(* Logix 5000 project; controller Test vendor 1 type 14 code 92 rev 33.11; software revision 33.03; part 2 of 2 *)
(* tags used below, declared in another part *)
   S15STH : Banner_S15S_TH_v4;
   Port_Data : Banner_IOL_Port_v4;
   Port : DINT;
   Local_Control : DINT;
   Command_Being_Processed : BOOL;
   Index_Write_Inprocess : INT;
   Inprocess_Index : DINT;
   AOI_Out_Status : Banner_S15S_TH_Float_Out_v4[12];
(* Banner_S15S_TH_Param_v4, continued *)

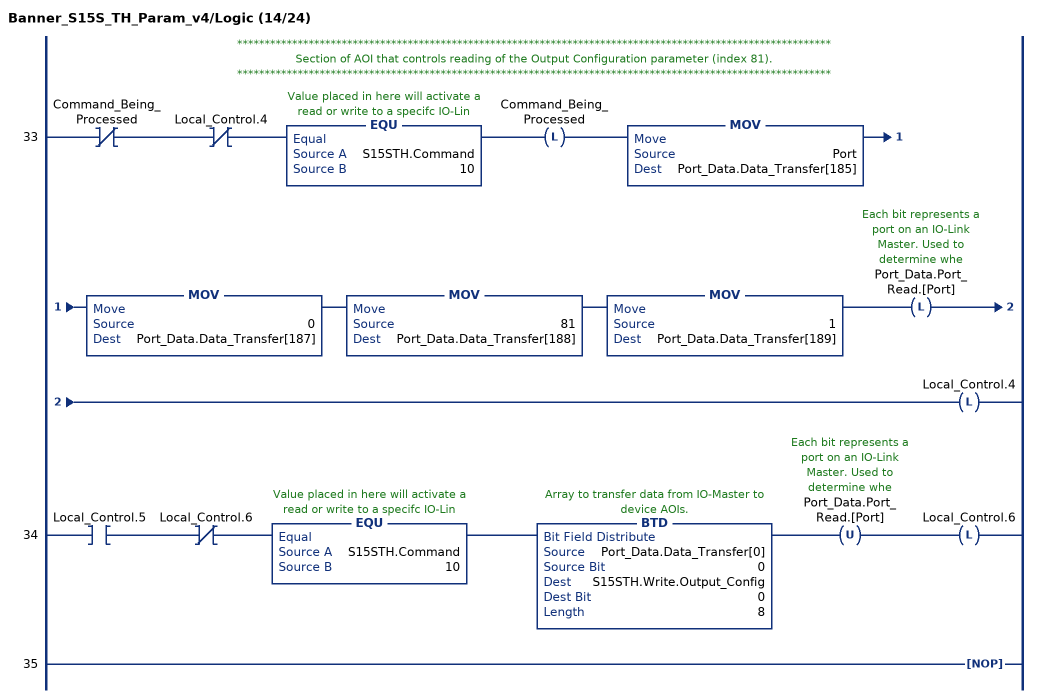
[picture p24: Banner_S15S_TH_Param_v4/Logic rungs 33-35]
   // ************************************************************************************************************
   // Section of AOI that controls reading of the Output Configuration parameter (index 81).
   // ************************************************************************************************************
   33: XIO(Command_Being_Processed)XIO(Local_Control.4)EQU(S15STH.Command,10)OTL(Command_Being_Processed)MOV(Port,Port_Data.Data_Transfer[185])MOV(0,Port_Data.Data_Transfer[187])MOV(81,Port_Data.Data_Transfer[188])MOV(1,Port_Data.Data_Transfer[189])OTL(Port_Data.Port_Read.[Port])OTL(Local_Control.4);
   34: XIC(Local_Control.5)XIO(Local_Control.6)EQU(S15STH.Command,10)BTD(Port_Data.Data_Transfer[0],0,S15STH.Write.Output_Config,0,8)OTU(Port_Data.Port_Read.[Port])OTL(Local_Control.6);
   35: NOP();
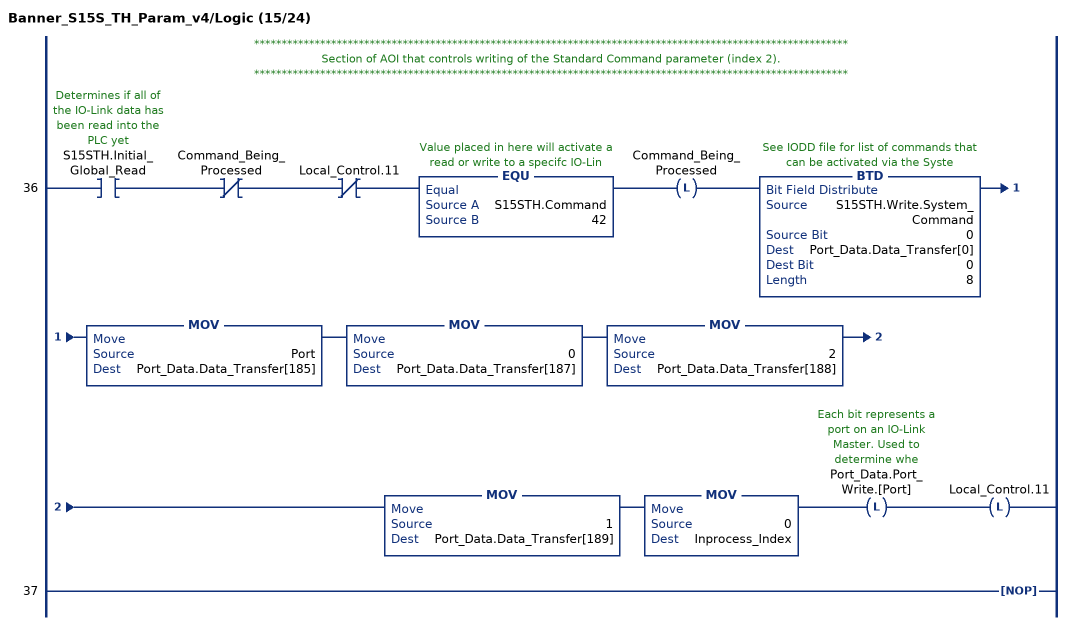
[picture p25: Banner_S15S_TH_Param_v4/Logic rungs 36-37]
   // ************************************************************************************************************
   // Section of AOI that controls writing of the Standard Command parameter (index 2).
   // ************************************************************************************************************
   36: XIC(S15STH.Initial_Global_Read)XIO(Command_Being_Processed)XIO(Local_Control.11)EQU(S15STH.Command,42)OTL(Command_Being_Processed)BTD(S15STH.Write.System_Command,0,Port_Data.Data_Transfer[0],0,8)MOV(Port,Port_Data.Data_Transfer[185])MOV(0,Port_Data.Data_Transfer[187])MOV(2,Port_Data.Data_Transfer[188])MOV(1,Port_Data.Data_Transfer[189])MOV(0,Inprocess_Index)OTL(Port_Data.Port_Write.[Port])OTL(Local_Control.11);
   37: NOP();
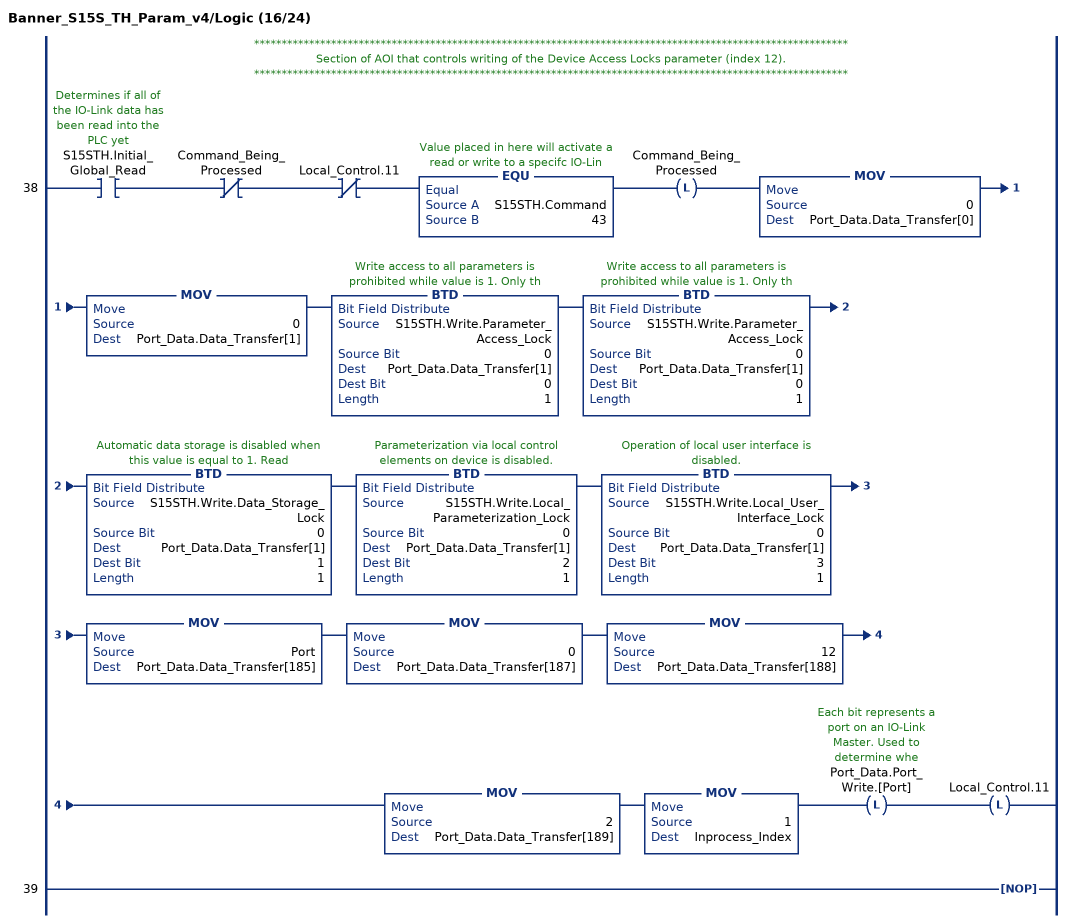
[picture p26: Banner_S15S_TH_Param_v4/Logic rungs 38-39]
   // ************************************************************************************************************
   // Section of AOI that controls writing of the Device Access Locks parameter (index 12).
   // ************************************************************************************************************
   38: XIC(S15STH.Initial_Global_Read)XIO(Command_Being_Processed)XIO(Local_Control.11)EQU(S15STH.Command,43)OTL(Command_Being_Processed)MOV(0,Port_Data.Data_Transfer[0])MOV(0,Port_Data.Data_Transfer[1])BTD(S15STH.Write.Parameter_Access_Lock,0,Port_Data.Data_Transfer[1],0,1)BTD(S15STH.Write.Parameter_Access_Lock,0,Port_Data.Data_Transfer[1],0,1)BTD(S15STH.Write.Data_Storage_Lock,0,Port_Data.Data_Transfer[1],1,1)BTD(S15STH.Write.Local_Parameterization_Lock,0,Port_Data.Data_Transfer[1],2,1)BTD(S15STH.Write.Local_User_Interface_Lock,0,Port_Data.Data_Transfer[1],3,1)MOV(Port,Port_Data.Data_Transfer[185])MOV(0,Port_Data.Data_Transfer[187])MOV(12,Port_Data.Data_Transfer[188])MOV(2,Port_Data.Data_Transfer[189])MOV(1,Inprocess_Index)OTL(Port_Data.Port_Write.[Port])OTL(Local_Control.11);
   39: NOP();
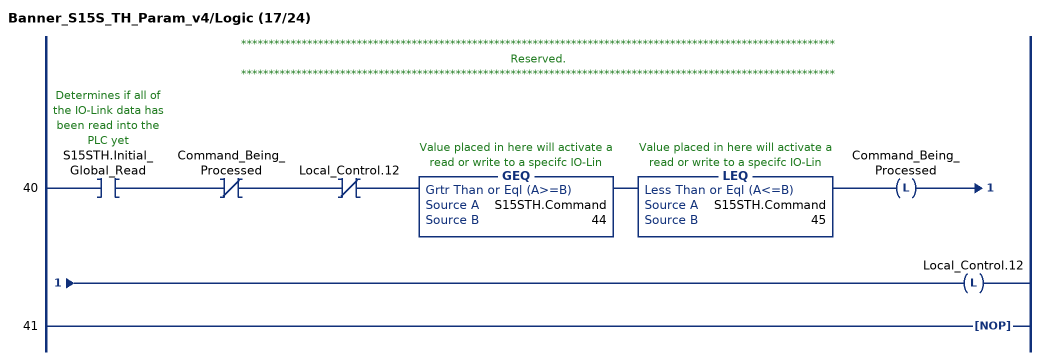
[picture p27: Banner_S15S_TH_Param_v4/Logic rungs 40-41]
   // ************************************************************************************************************
   // Reserved.
   // ************************************************************************************************************
   40: XIC(S15STH.Initial_Global_Read)XIO(Command_Being_Processed)XIO(Local_Control.12)GEQ(S15STH.Command,44)LEQ(S15STH.Command,45)OTL(Command_Being_Processed)OTL(Local_Control.12);
   41: NOP();
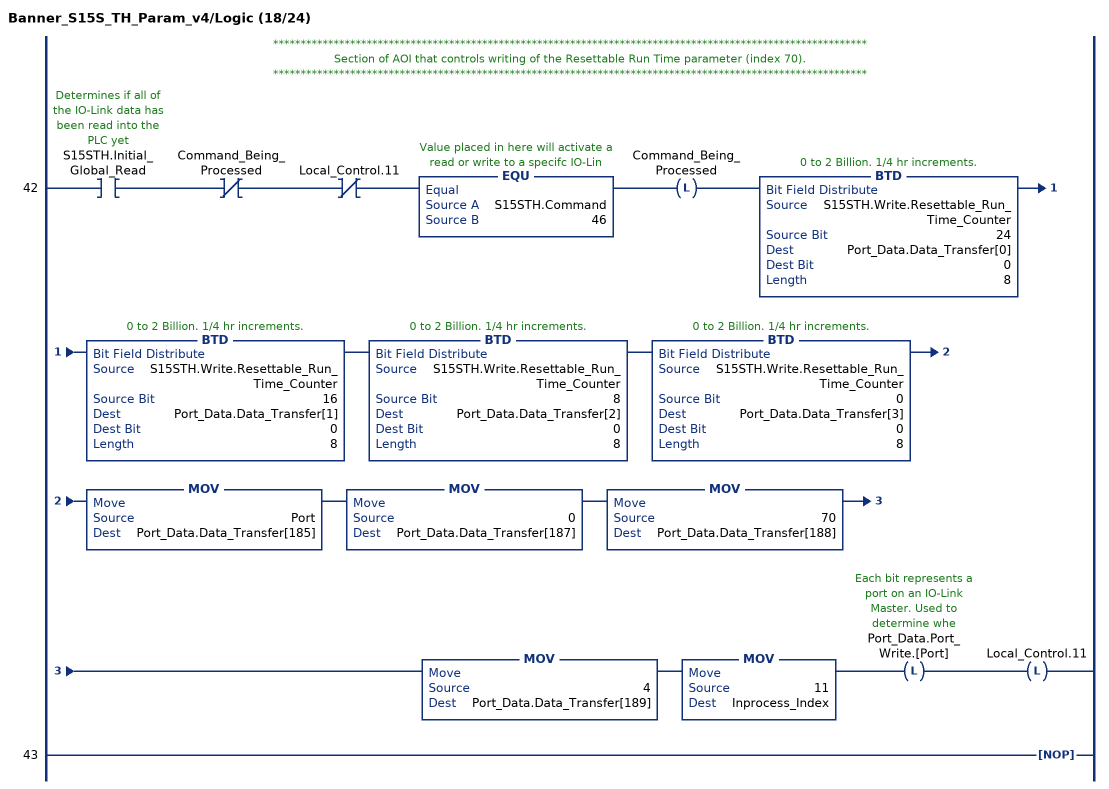
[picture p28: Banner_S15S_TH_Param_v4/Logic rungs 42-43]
   // ************************************************************************************************************
   // Section of AOI that controls writing of the Resettable Run Time parameter (index 70).
   // ************************************************************************************************************
   42: XIC(S15STH.Initial_Global_Read)XIO(Command_Being_Processed)XIO(Local_Control.11)EQU(S15STH.Command,46)OTL(Command_Being_Processed)BTD(S15STH.Write.Resettable_Run_Time_Counter,24,Port_Data.Data_Transfer[0],0,8)BTD(S15STH.Write.Resettable_Run_Time_Counter,16,Port_Data.Data_Transfer[1],0,8)BTD(S15STH.Write.Resettable_Run_Time_Counter,8,Port_Data.Data_Transfer[2],0,8)BTD(S15STH.Write.Resettable_Run_Time_Counter,0,Port_Data.Data_Transfer[3],0,8)MOV(Port,Port_Data.Data_Transfer[185])MOV(0,Port_Data.Data_Transfer[187])MOV(70,Port_Data.Data_Transfer[188])MOV(4,Port_Data.Data_Transfer[189])MOV(11,Inprocess_Index)OTL(Port_Data.Port_Write.[Port])OTL(Local_Control.11);
   43: NOP();
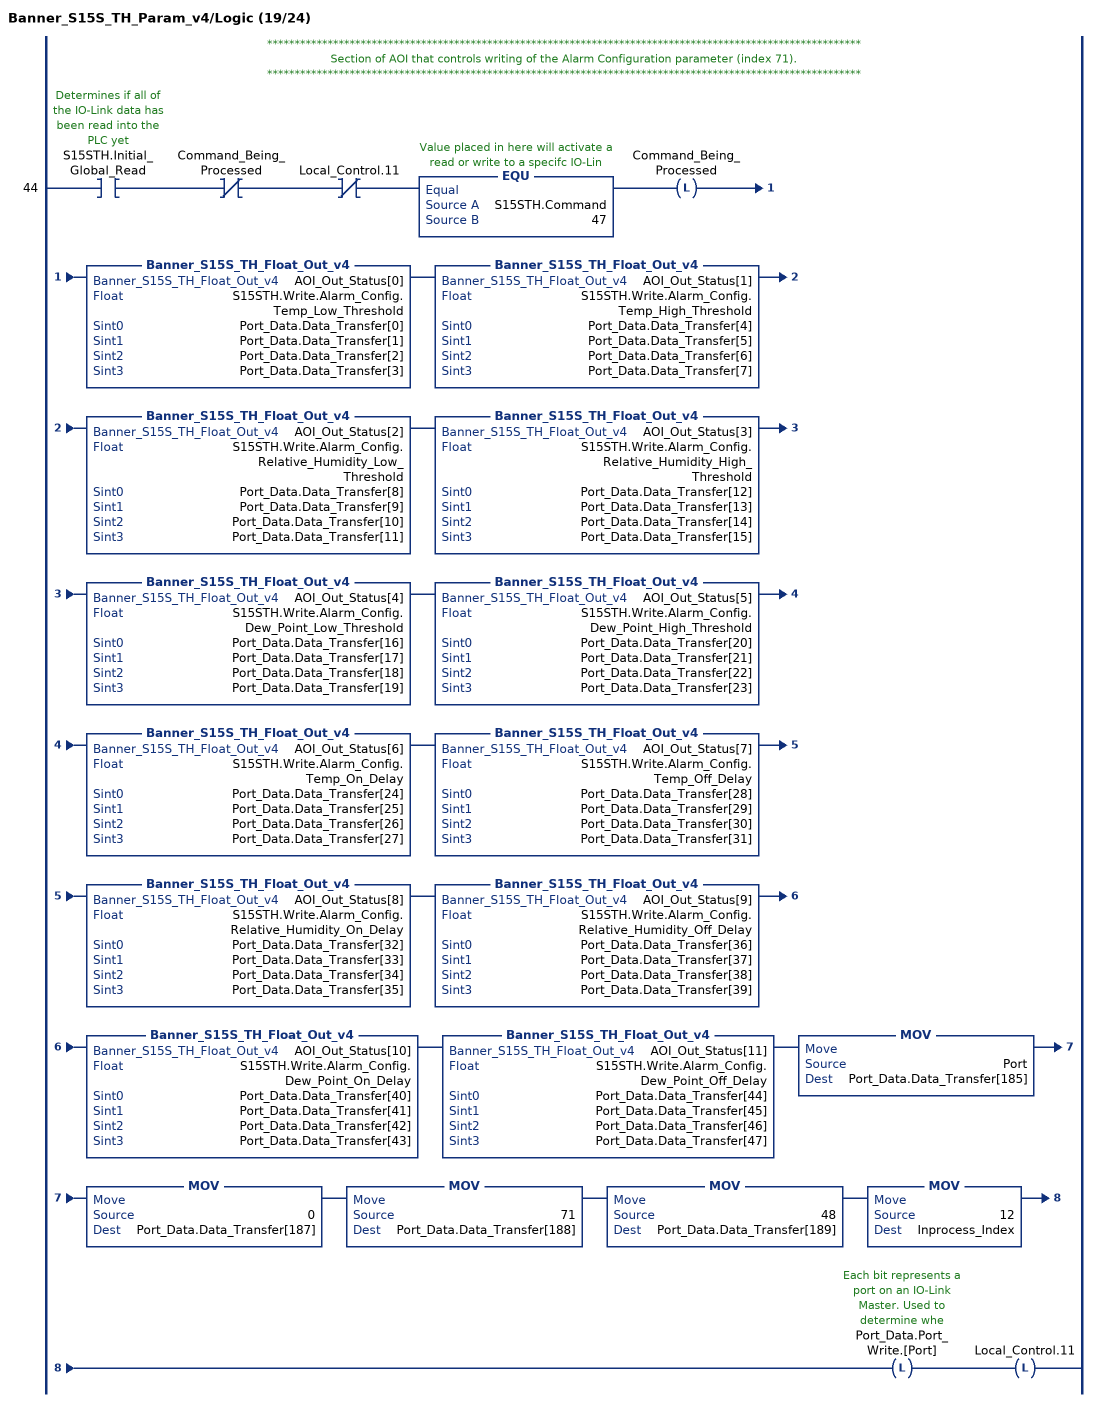
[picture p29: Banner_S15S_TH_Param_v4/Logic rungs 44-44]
   // ************************************************************************************************************
   // Section of AOI that controls writing of the Alarm Configuration parameter (index 71).
   // ************************************************************************************************************
   44: XIC(S15STH.Initial_Global_Read)XIO(Command_Being_Processed)XIO(Local_Control.11)EQU(S15STH.Command,47)OTL(Command_Being_Processed)Banner_S15S_TH_Float_Out_v4(AOI_Out_Status[0],S15STH.Write.Alarm_Config.Temp_Low_Threshold,Port_Data.Data_Transfer[0],Port_Data.Data_Transfer[1],Port_Data.Data_Transfer[2],Port_Data.Data_Transfer[3])Banner_S15S_TH_Float_Out_v4(AOI_Out_Status[1],S15STH.Write.Alarm_Config.Temp_High_Threshold,Port_Data.Data_Transfer[4],Port_Data.Data_Transfer[5],Port_Data.Data_Transfer[6],Port_Data.Data_Transfer[7])Banner_S15S_TH_Float_Out_v4(AOI_Out_Status[2],S15STH.Write.Alarm_Config.Relative_Humidity_Low_Threshold,Port_Data.Data_Transfer[8],Port_Data.Data_Transfer[9],Port_Data.Data_Transfer[10],Port_Data.Data_Transfer[11])Banner_S15S_TH_Float_Out_v4(AOI_Out_Status[3],S15STH.Write.Alarm_Config.Relative_Humidity_High_Threshold,Port_Data.Data_Transfer[12],Port_Data.Data_Transfer[13],Port_Data.Data_Transfer[14],Port_Data.Data_Transfer[15])Banner_S15S_TH_Float_Out_v4(AOI_Out_Status[4],S15STH.Write.Alarm_Config.Dew_Point_Low_Threshold,Port_Data.Data_Transfer[16],Port_Data.Data_Transfer[17],Port_Data.Data_Transfer[18],Port_Data.Data_Transfer[19])Banner_S15S_TH_Float_Out_v4(AOI_Out_Status[5],S15STH.Write.Alarm_Config.Dew_Point_High_Threshold,Port_Data.Data_Transfer[20],Port_Data.Data_Transfer[21],Port_Data.Data_Transfer[22],Port_Data.Data_Transfer[23])Banner_S15S_TH_Float_Out_v4(AOI_Out_Status[6],S15STH.Write.Alarm_Config.Temp_On_Delay,Port_Data.Data_Transfer[24],Port_Data.Data_Transfer[25],Port_Data.Data_Transfer[26],Port_Data.Data_Transfer[27])Banner_S15S_TH_Float_Out_v4(AOI_Out_Status[7],S15STH.Write.Alarm_Config.Temp_Off_Delay,Port_Data.Data_Transfer[28],Port_Data.Data_Transfer[29],Port_Data.Data_Transfer[30],Port_Data.Data_Transfer[31])Banner_S15S_TH_Float_Out_v4(AOI_Out_Status[8],S15STH.Write.Alarm_Config.Relative_Humidity_On_Delay,Port_Data.Data_Transfer[32],Port_Data.Data_Transfer[33],Port_Data.Data_Transfer[34],Port_Data.Data_Transfer[35])Banner_S15S_TH_Float_Out_v4(AOI_Out_Status[9],S15STH.Write.Alarm_Config.Relative_Humidity_Off_Delay,Port_Data.Data_Transfer[36],Port_Data.Data_Transfer[37],Port_Data.Data_Transfer[38],Port_Data.Data_Transfer[39])Banner_S15S_TH_Float_Out_v4(AOI_Out_Status[10],S15STH.Write.Alarm_Config.Dew_Point_On_Delay,Port_Data.Data_Transfer[40],Port_Data.Data_Transfer[41],Port_Data.Data_Transfer[42],Port_Data.Data_Transfer[43])Banner_S15S_TH_Float_Out_v4(AOI_Out_Status[11],S15STH.Write.Alarm_Config.Dew_Point_Off_Delay,Port_Data.Data_Transfer[44],Port_Data.Data_Transfer[45],Port_Data.Data_Transfer[46],Port_Data.Data_Transfer[47])MOV(Port,Port_Data.Data_Transfer[185])MOV(0,Port_Data.Data_Transfer[187])MOV(71,Port_Data.Data_Transfer[188])MOV(48,Port_Data.Data_Transfer[189])MOV(12,Inprocess_Index)OTL(Port_Data.Port_Write.[Port])OTL(Local_Control.11);
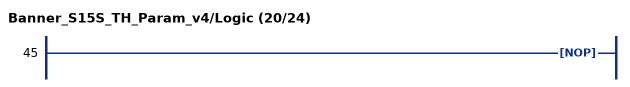
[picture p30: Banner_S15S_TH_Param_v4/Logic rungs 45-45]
   45: NOP();
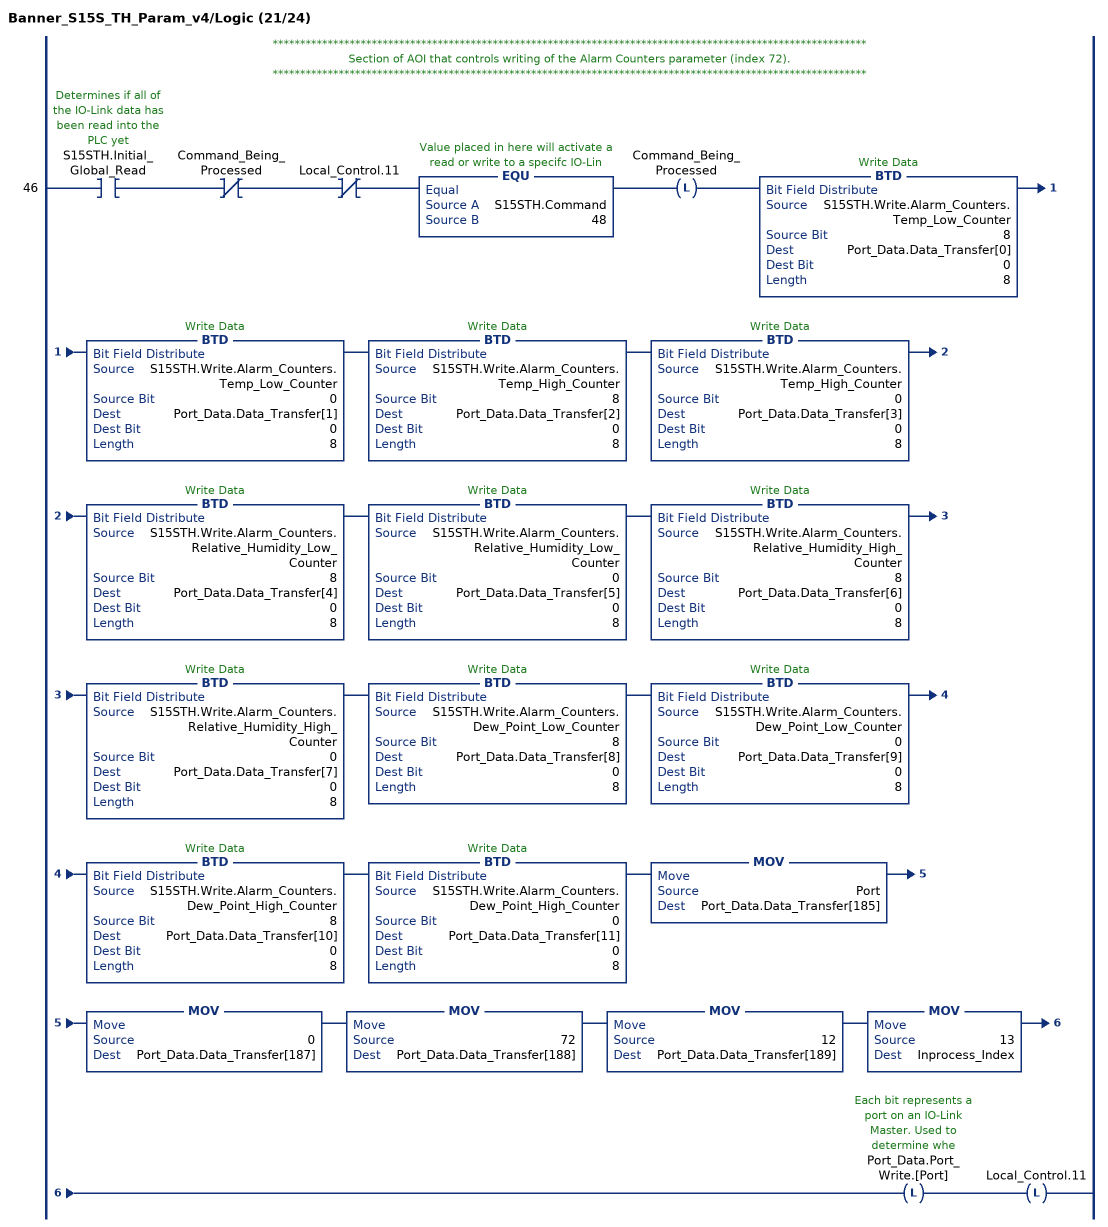
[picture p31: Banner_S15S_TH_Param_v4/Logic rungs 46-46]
   // ************************************************************************************************************
   // Section of AOI that controls writing of the Alarm Counters parameter (index 72).
   // ************************************************************************************************************
   46: XIC(S15STH.Initial_Global_Read)XIO(Command_Being_Processed)XIO(Local_Control.11)EQU(S15STH.Command,48)OTL(Command_Being_Processed)BTD(S15STH.Write.Alarm_Counters.Temp_Low_Counter,8,Port_Data.Data_Transfer[0],0,8)BTD(S15STH.Write.Alarm_Counters.Temp_Low_Counter,0,Port_Data.Data_Transfer[1],0,8)BTD(S15STH.Write.Alarm_Counters.Temp_High_Counter,8,Port_Data.Data_Transfer[2],0,8)BTD(S15STH.Write.Alarm_Counters.Temp_High_Counter,0,Port_Data.Data_Transfer[3],0,8)BTD(S15STH.Write.Alarm_Counters.Relative_Humidity_Low_Counter,8,Port_Data.Data_Transfer[4],0,8)BTD(S15STH.Write.Alarm_Counters.Relative_Humidity_Low_Counter,0,Port_Data.Data_Transfer[5],0,8)BTD(S15STH.Write.Alarm_Counters.Relative_Humidity_High_Counter,8,Port_Data.Data_Transfer[6],0,8)BTD(S15STH.Write.Alarm_Counters.Relative_Humidity_High_Counter,0,Port_Data.Data_Transfer[7],0,8)BTD(S15STH.Write.Alarm_Counters.Dew_Point_Low_Counter,8,Port_Data.Data_Transfer[8],0,8)BTD(S15STH.Write.Alarm_Counters.Dew_Point_Low_Counter,0,Port_Data.Data_Transfer[9],0,8)BTD(S15STH.Write.Alarm_Counters.Dew_Point_High_Counter,8,Port_Data.Data_Transfer[10],0,8)BTD(S15STH.Write.Alarm_Counters.Dew_Point_High_Counter,0,Port_Data.Data_Transfer[11],0,8)MOV(Port,Port_Data.Data_Transfer[185])MOV(0,Port_Data.Data_Transfer[187])MOV(72,Port_Data.Data_Transfer[188])MOV(12,Port_Data.Data_Transfer[189])MOV(13,Inprocess_Index)OTL(Port_Data.Port_Write.[Port])OTL(Local_Control.11);
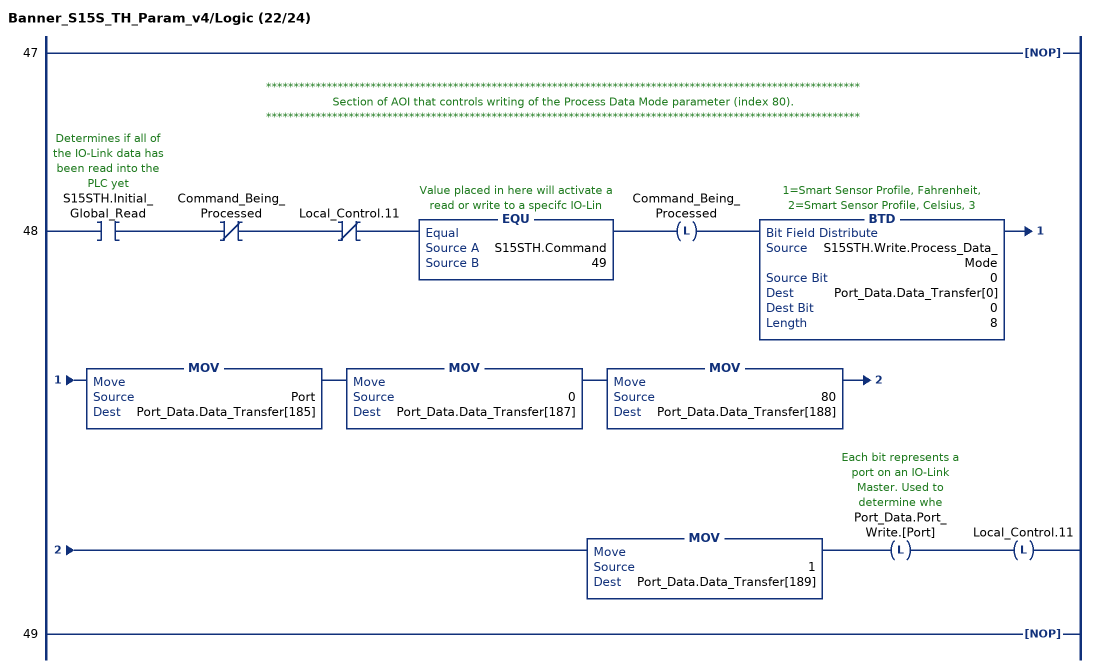
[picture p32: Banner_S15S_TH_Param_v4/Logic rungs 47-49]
   47: NOP();
   // ************************************************************************************************************
   // Section of AOI that controls writing of the Process Data Mode parameter (index 80).
   // ************************************************************************************************************
   48: XIC(S15STH.Initial_Global_Read)XIO(Command_Being_Processed)XIO(Local_Control.11)EQU(S15STH.Command,49)OTL(Command_Being_Processed)BTD(S15STH.Write.Process_Data_Mode,0,Port_Data.Data_Transfer[0],0,8)MOV(Port,Port_Data.Data_Transfer[185])MOV(0,Port_Data.Data_Transfer[187])MOV(80,Port_Data.Data_Transfer[188])MOV(1,Port_Data.Data_Transfer[189])OTL(Port_Data.Port_Write.[Port])OTL(Local_Control.11);
   49: NOP();
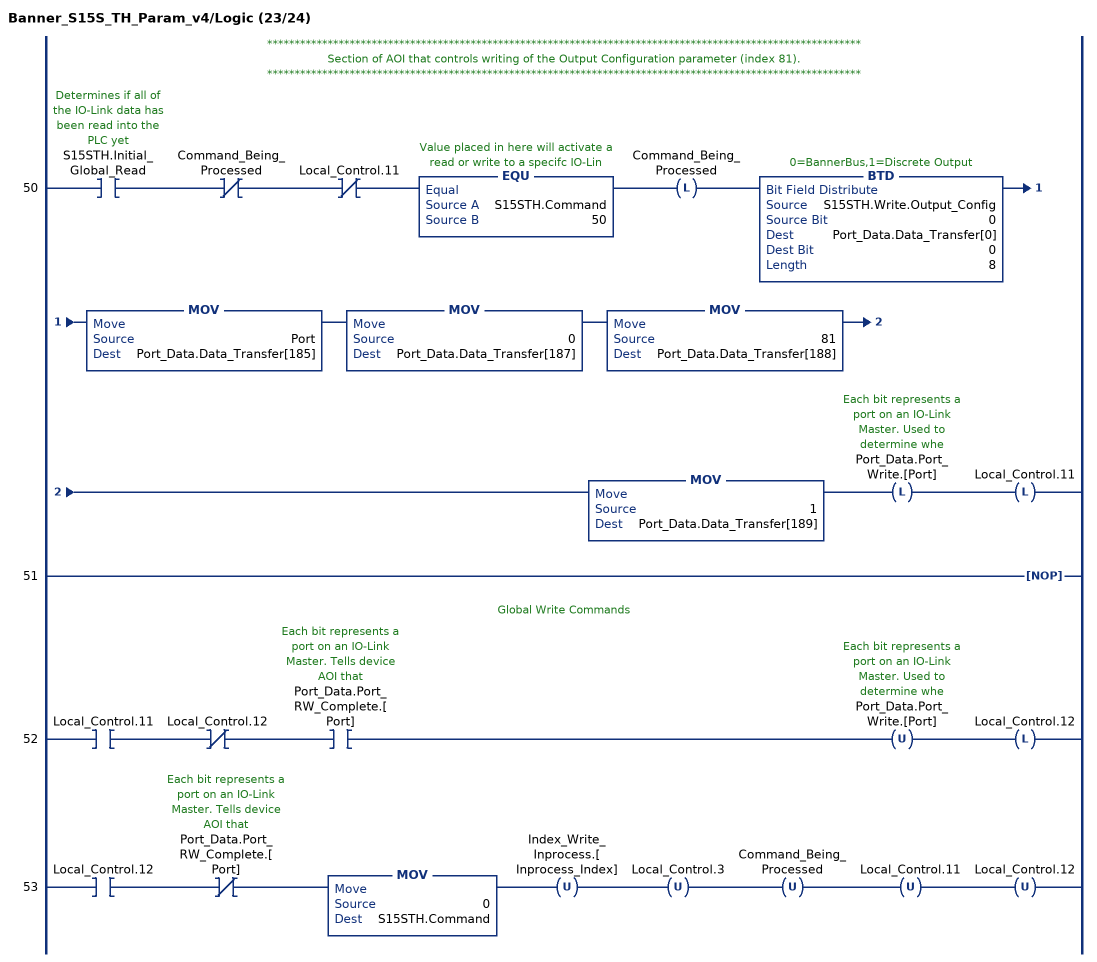
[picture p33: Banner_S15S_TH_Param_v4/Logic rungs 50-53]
   // ************************************************************************************************************
   // Section of AOI that controls writing of the Output Configuration parameter (index 81).
   // ************************************************************************************************************
   50: XIC(S15STH.Initial_Global_Read)XIO(Command_Being_Processed)XIO(Local_Control.11)EQU(S15STH.Command,50)OTL(Command_Being_Processed)BTD(S15STH.Write.Output_Config,0,Port_Data.Data_Transfer[0],0,8)MOV(Port,Port_Data.Data_Transfer[185])MOV(0,Port_Data.Data_Transfer[187])MOV(81,Port_Data.Data_Transfer[188])MOV(1,Port_Data.Data_Transfer[189])OTL(Port_Data.Port_Write.[Port])OTL(Local_Control.11);
   51: NOP();
   // Global Write Commands
   52: XIC(Local_Control.11)XIO(Local_Control.12)XIC(Port_Data.Port_RW_Complete.[Port])OTU(Port_Data.Port_Write.[Port])OTL(Local_Control.12);
   53: XIC(Local_Control.12)XIO(Port_Data.Port_RW_Complete.[Port])MOV(0,S15STH.Command)OTU(Index_Write_Inprocess.[Inprocess_Index])OTU(Local_Control.3)OTU(Command_Being_Processed)OTU(Local_Control.11)OTU(Local_Control.12);
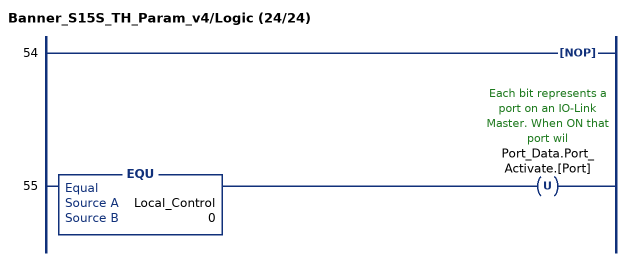
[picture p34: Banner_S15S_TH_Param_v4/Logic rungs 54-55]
   54: NOP();
   55: EQU(Local_Control,0)OTU(Port_Data.Port_Activate.[Port]);
END_ROUTINE
END_ADD_ON_INSTRUCTION

ADD_ON_INSTRUCTION Banner_S15S_TH_PD_v4   (* revision 4.0, vendor Banner Engineering *)
// Take raw process data and convert it to usable values.
VAR_IN_OUT
   PD : Banner_S15S_TH_PDI_v4; {required}
END_VAR
VAR_INPUT
   Operation_Mode : INT; {required}
   Byte_Swap : BOOL; {required}
END_VAR
VAR
   Temp_Byte : SINT[16]; {access None}
   AOI_In_Status : Banner_S15S_TH_Float_In_v4[3]; {access None}
END_VAR

ROUTINE Logic   (* ladder *)
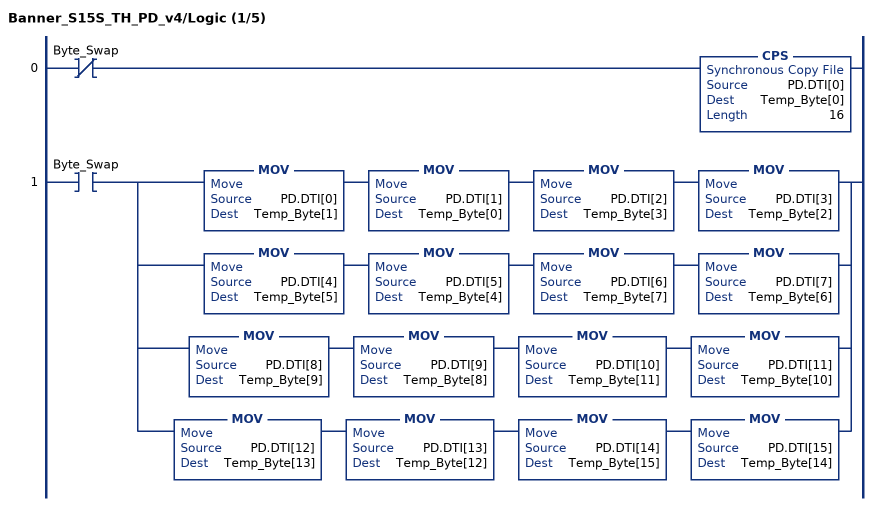
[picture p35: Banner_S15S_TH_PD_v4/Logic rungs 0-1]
   0: XIO(Byte_Swap)CPS(PD.DTI[0],Temp_Byte[0],16);
   1: XIC(Byte_Swap)[MOV(PD.DTI[0],Temp_Byte[1]) MOV(PD.DTI[1],Temp_Byte[0]) MOV(PD.DTI[2],Temp_Byte[3]) MOV(PD.DTI[3],Temp_Byte[2]) ,MOV(PD.DTI[4],Temp_Byte[5]) MOV(PD.DTI[5],Temp_Byte[4]) MOV(PD.DTI[6],Temp_Byte[7]) MOV(PD.DTI[7],Temp_Byte[6]) ,MOV(PD.DTI[8],Temp_Byte[9]) MOV(PD.DTI[9],Temp_Byte[8]) MOV(PD.DTI[10],Temp_Byte[11]) MOV(PD.DTI[11],Temp_Byte[10]) ,MOV(PD.DTI[12],Temp_Byte[13]) MOV(PD.DTI[13],Temp_Byte[12]) MOV(PD.DTI[14],Temp_Byte[15]) MOV(PD.DTI[15],Temp_Byte[14]) ];
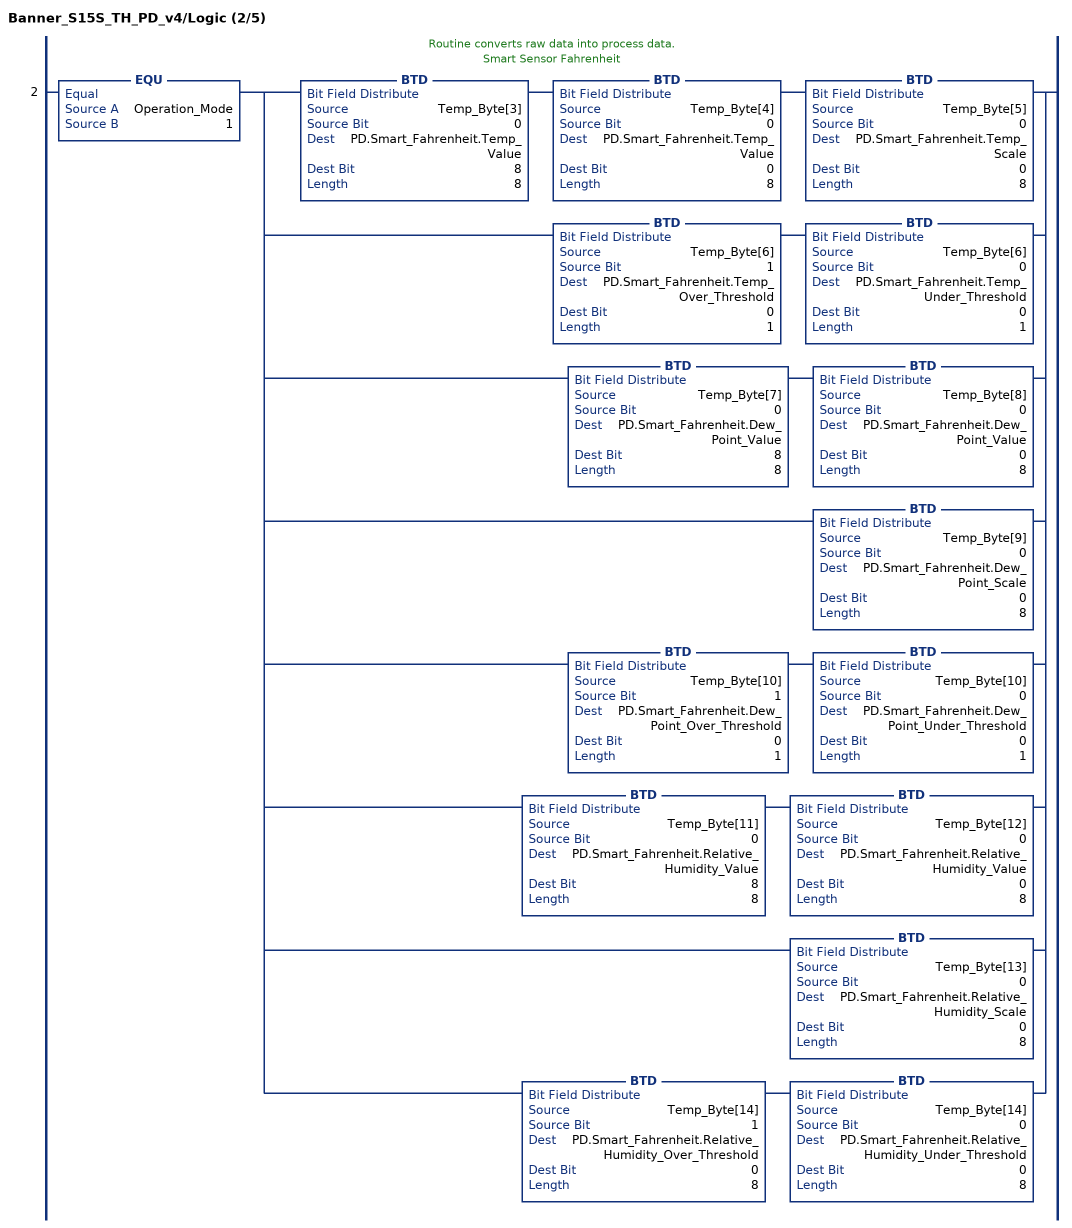
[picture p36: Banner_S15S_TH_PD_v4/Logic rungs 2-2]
   // Routine converts raw data into process data.
   // Smart Sensor Fahrenheit
   2: EQU(Operation_Mode,1)[BTD(Temp_Byte[3],0,PD.Smart_Fahrenheit.Temp_Value,8,8) BTD(Temp_Byte[4],0,PD.Smart_Fahrenheit.Temp_Value,0,8) BTD(Temp_Byte[5],0,PD.Smart_Fahrenheit.Temp_Scale,0,8) ,BTD(Temp_Byte[6],1,PD.Smart_Fahrenheit.Temp_Over_Threshold,0,1) BTD(Temp_Byte[6],0,PD.Smart_Fahrenheit.Temp_Under_Threshold,0,1) ,BTD(Temp_Byte[7],0,PD.Smart_Fahrenheit.Dew_Point_Value,8,8) BTD(Temp_Byte[8],0,PD.Smart_Fahrenheit.Dew_Point_Value,0,8) ,BTD(Temp_Byte[9],0,PD.Smart_Fahrenheit.Dew_Point_Scale,0,8) ,BTD(Temp_Byte[10],1,PD.Smart_Fahrenheit.Dew_Point_Over_Threshold,0,1) BTD(Temp_Byte[10],0,PD.Smart_Fahrenheit.Dew_Point_Under_Threshold,0,1) ,BTD(Temp_Byte[11],0,PD.Smart_Fahrenheit.Relative_Humidity_Value,8,8) BTD(Temp_Byte[12],0,PD.Smart_Fahrenheit.Relative_Humidity_Value,0,8) ,BTD(Temp_Byte[13],0,PD.Smart_Fahrenheit.Relative_Humidity_Scale,0,8) ,BTD(Temp_Byte[14],1,PD.Smart_Fahrenheit.Relative_Humidity_Over_Threshold,0,8) BTD(Temp_Byte[14],0,PD.Smart_Fahrenheit.Relative_Humidity_Under_Threshold,0,8) ];
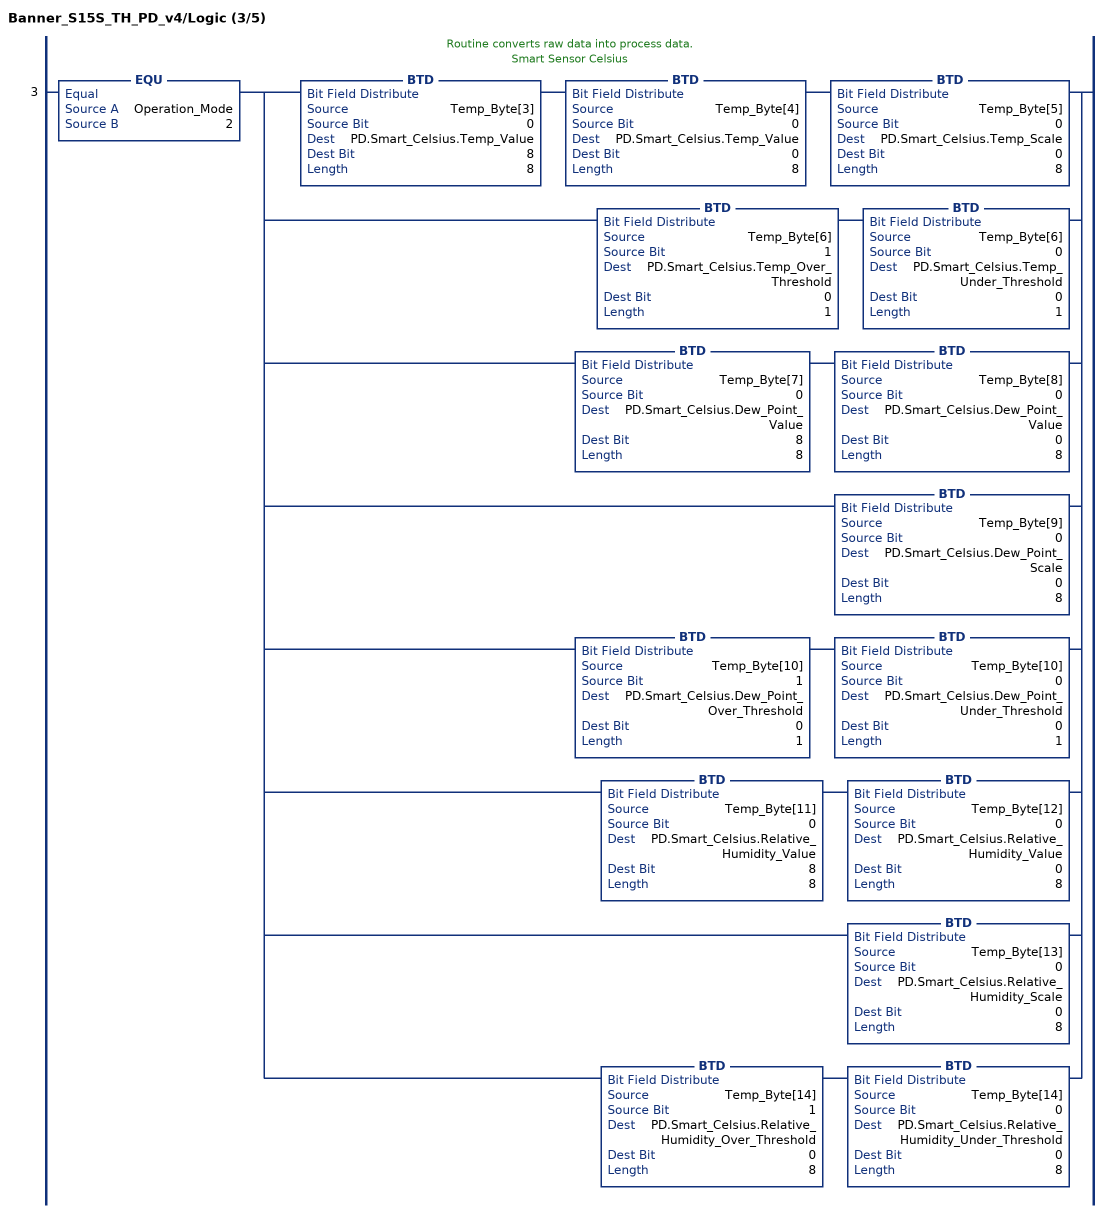
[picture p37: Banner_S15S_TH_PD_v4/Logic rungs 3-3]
   // Routine converts raw data into process data.
   // Smart Sensor Celsius
   3: EQU(Operation_Mode,2)[BTD(Temp_Byte[3],0,PD.Smart_Celsius.Temp_Value,8,8) BTD(Temp_Byte[4],0,PD.Smart_Celsius.Temp_Value,0,8) BTD(Temp_Byte[5],0,PD.Smart_Celsius.Temp_Scale,0,8) ,BTD(Temp_Byte[6],1,PD.Smart_Celsius.Temp_Over_Threshold,0,1) BTD(Temp_Byte[6],0,PD.Smart_Celsius.Temp_Under_Threshold,0,1) ,BTD(Temp_Byte[7],0,PD.Smart_Celsius.Dew_Point_Value,8,8) BTD(Temp_Byte[8],0,PD.Smart_Celsius.Dew_Point_Value,0,8) ,BTD(Temp_Byte[9],0,PD.Smart_Celsius.Dew_Point_Scale,0,8) ,BTD(Temp_Byte[10],1,PD.Smart_Celsius.Dew_Point_Over_Threshold,0,1) BTD(Temp_Byte[10],0,PD.Smart_Celsius.Dew_Point_Under_Threshold,0,1) ,BTD(Temp_Byte[11],0,PD.Smart_Celsius.Relative_Humidity_Value,8,8) BTD(Temp_Byte[12],0,PD.Smart_Celsius.Relative_Humidity_Value,0,8) ,BTD(Temp_Byte[13],0,PD.Smart_Celsius.Relative_Humidity_Scale,0,8) ,BTD(Temp_Byte[14],1,PD.Smart_Celsius.Relative_Humidity_Over_Threshold,0,8) BTD(Temp_Byte[14],0,PD.Smart_Celsius.Relative_Humidity_Under_Threshold,0,8) ];
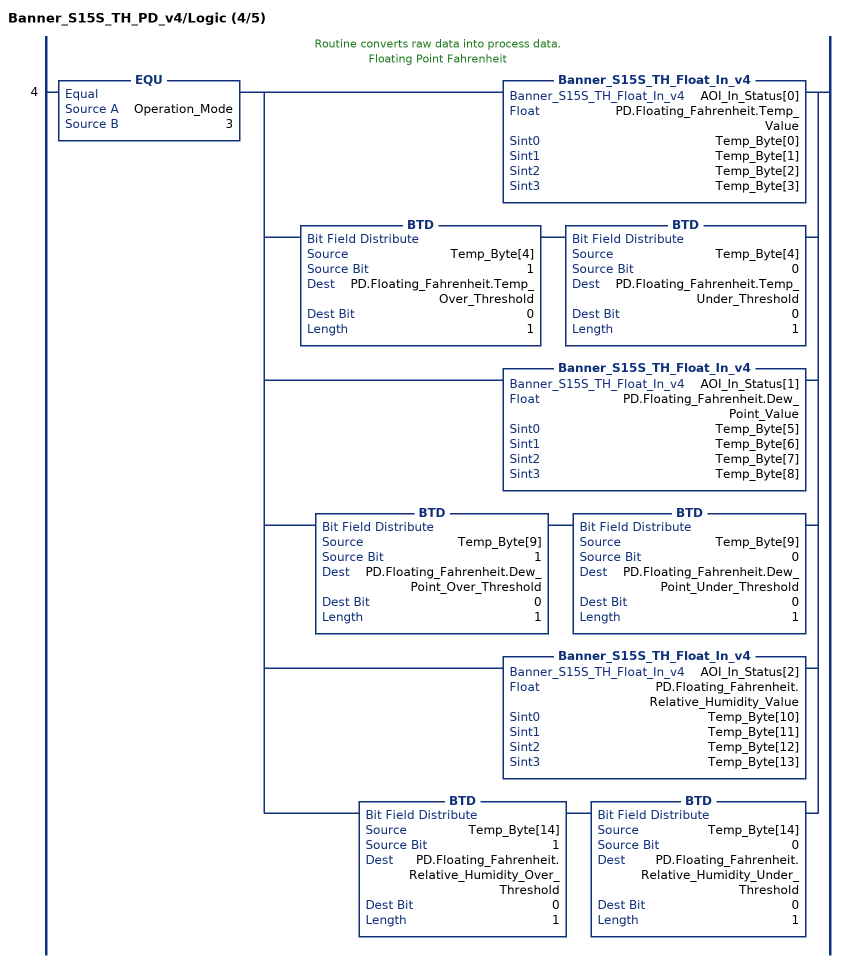
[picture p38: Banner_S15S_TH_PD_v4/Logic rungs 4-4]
   // Routine converts raw data into process data.
   // Floating Point Fahrenheit
   4: EQU(Operation_Mode,3)[Banner_S15S_TH_Float_In_v4(AOI_In_Status[0],PD.Floating_Fahrenheit.Temp_Value,Temp_Byte[0],Temp_Byte[1],Temp_Byte[2],Temp_Byte[3]) ,BTD(Temp_Byte[4],1,PD.Floating_Fahrenheit.Temp_Over_Threshold,0,1) BTD(Temp_Byte[4],0,PD.Floating_Fahrenheit.Temp_Under_Threshold,0,1) ,Banner_S15S_TH_Float_In_v4(AOI_In_Status[1],PD.Floating_Fahrenheit.Dew_Point_Value,Temp_Byte[5],Temp_Byte[6],Temp_Byte[7],Temp_Byte[8]) ,BTD(Temp_Byte[9],1,PD.Floating_Fahrenheit.Dew_Point_Over_Threshold,0,1) BTD(Temp_Byte[9],0,PD.Floating_Fahrenheit.Dew_Point_Under_Threshold,0,1) ,Banner_S15S_TH_Float_In_v4(AOI_In_Status[2],PD.Floating_Fahrenheit.Relative_Humidity_Value,Temp_Byte[10],Temp_Byte[11],Temp_Byte[12],Temp_Byte[13]) ,BTD(Temp_Byte[14],1,PD.Floating_Fahrenheit.Relative_Humidity_Over_Threshold,0,1) BTD(Temp_Byte[14],0,PD.Floating_Fahrenheit.Relative_Humidity_Under_Threshold,0,1) ];
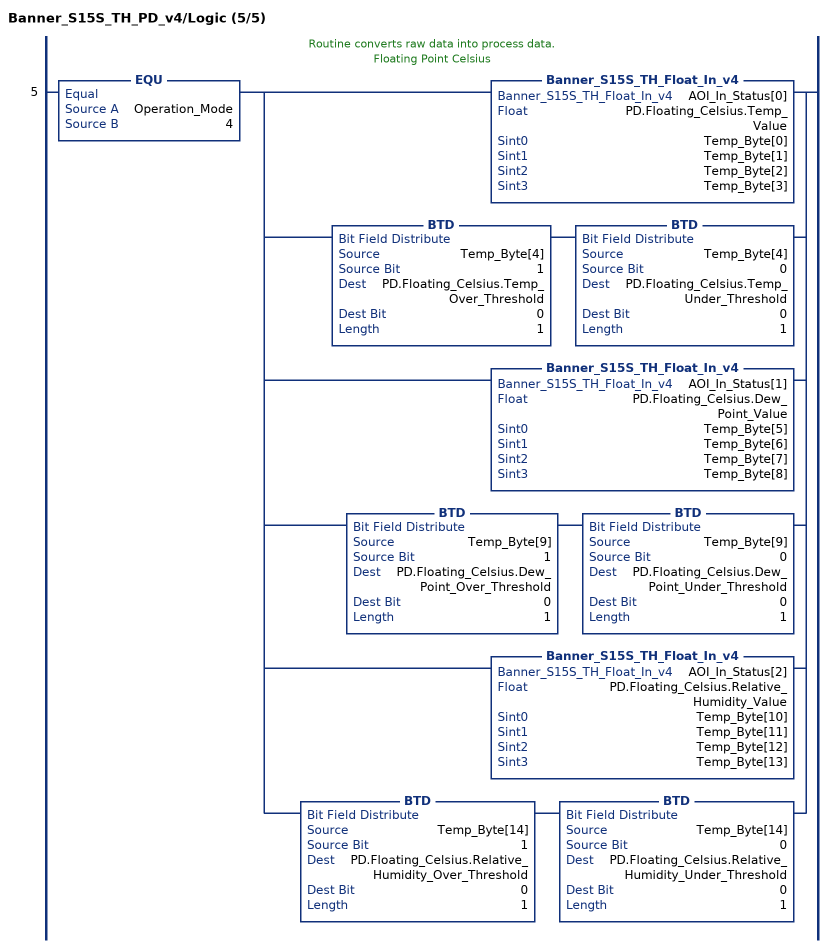
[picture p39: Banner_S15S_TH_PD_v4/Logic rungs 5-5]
   // Routine converts raw data into process data.
   // Floating Point Celsius
   5: EQU(Operation_Mode,4)[Banner_S15S_TH_Float_In_v4(AOI_In_Status[0],PD.Floating_Celsius.Temp_Value,Temp_Byte[0],Temp_Byte[1],Temp_Byte[2],Temp_Byte[3]) ,BTD(Temp_Byte[4],1,PD.Floating_Celsius.Temp_Over_Threshold,0,1) BTD(Temp_Byte[4],0,PD.Floating_Celsius.Temp_Under_Threshold,0,1) ,Banner_S15S_TH_Float_In_v4(AOI_In_Status[1],PD.Floating_Celsius.Dew_Point_Value,Temp_Byte[5],Temp_Byte[6],Temp_Byte[7],Temp_Byte[8]) ,BTD(Temp_Byte[9],1,PD.Floating_Celsius.Dew_Point_Over_Threshold,0,1) BTD(Temp_Byte[9],0,PD.Floating_Celsius.Dew_Point_Under_Threshold,0,1) ,Banner_S15S_TH_Float_In_v4(AOI_In_Status[2],PD.Floating_Celsius.Relative_Humidity_Value,Temp_Byte[10],Temp_Byte[11],Temp_Byte[12],Temp_Byte[13]) ,BTD(Temp_Byte[14],1,PD.Floating_Celsius.Relative_Humidity_Over_Threshold,0,1) BTD(Temp_Byte[14],0,PD.Floating_Celsius.Relative_Humidity_Under_Threshold,0,1) ];
END_ROUTINE
END_ADD_ON_INSTRUCTION

VAR_GLOBAL   (* controller tags *)
   IOLM1 : Banner_IOLM_v4;
   IOLM1_Status : Banner_DXMR_IOLM_Param_v4;
   Reset : BOOL;
   S15S_TH_IOLM1_01 : Banner_S15S_TH_v4;
   S15S_TH_IOLM1_01_PD : Banner_S15S_TH_PDI_v4;
   S15S_TH_IOLM1_01_PD_Status : Banner_S15S_TH_PD_v4;
   S15S_TH_IOLM1_01_Status : Banner_S15S_TH_Param_v4;
END_VAR

PROGRAM MainProgram   (* main routine MainRoutine *)

ROUTINE MainRoutine   (* ladder *)
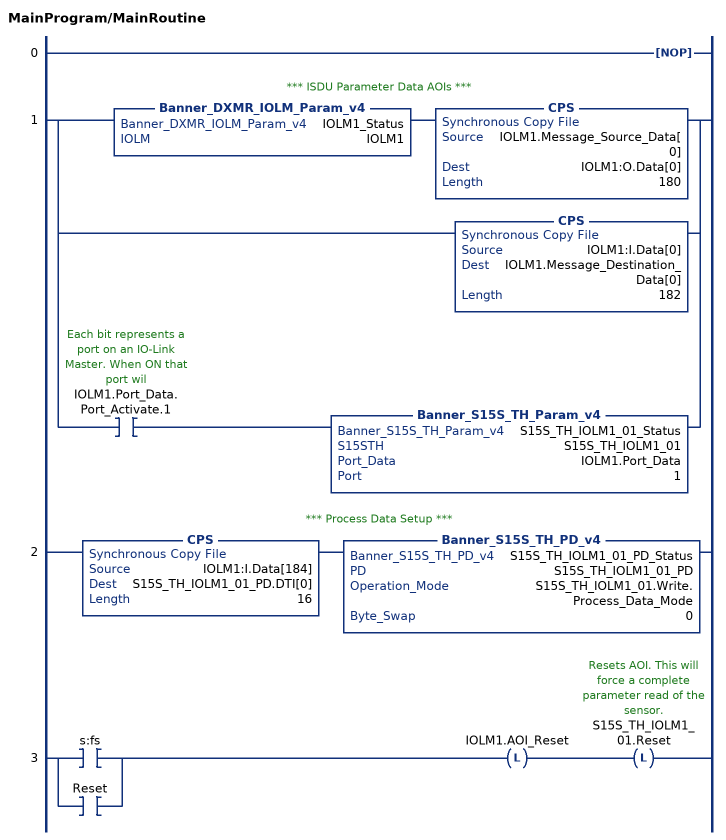
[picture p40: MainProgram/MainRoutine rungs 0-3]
   0: NOP();
   // *** ISDU Parameter Data AOIs ***
   1: [Banner_DXMR_IOLM_Param_v4(IOLM1_Status,IOLM1) CPS(IOLM1.Message_Source_Data[0],IOLM1:O.Data[0],180) ,CPS(IOLM1:I.Data[0],IOLM1.Message_Destination_Data[0],182) ,XIC(IOLM1.Port_Data.Port_Activate.1) Banner_S15S_TH_Param_v4(S15S_TH_IOLM1_01_Status,S15S_TH_IOLM1_01,IOLM1.Port_Data,1) ];
   // *** Process Data Setup ***
   2: CPS(IOLM1:I.Data[184],S15S_TH_IOLM1_01_PD.DTI[0],16)Banner_S15S_TH_PD_v4(S15S_TH_IOLM1_01_PD_Status,S15S_TH_IOLM1_01_PD,S15S_TH_IOLM1_01.Write.Process_Data_Mode,0);
   3: [XIC(s:fs) ,XIC(Reset) ]OTL(IOLM1.AOI_Reset)OTL(S15S_TH_IOLM1_01.Reset);
END_ROUTINE
END_PROGRAM
